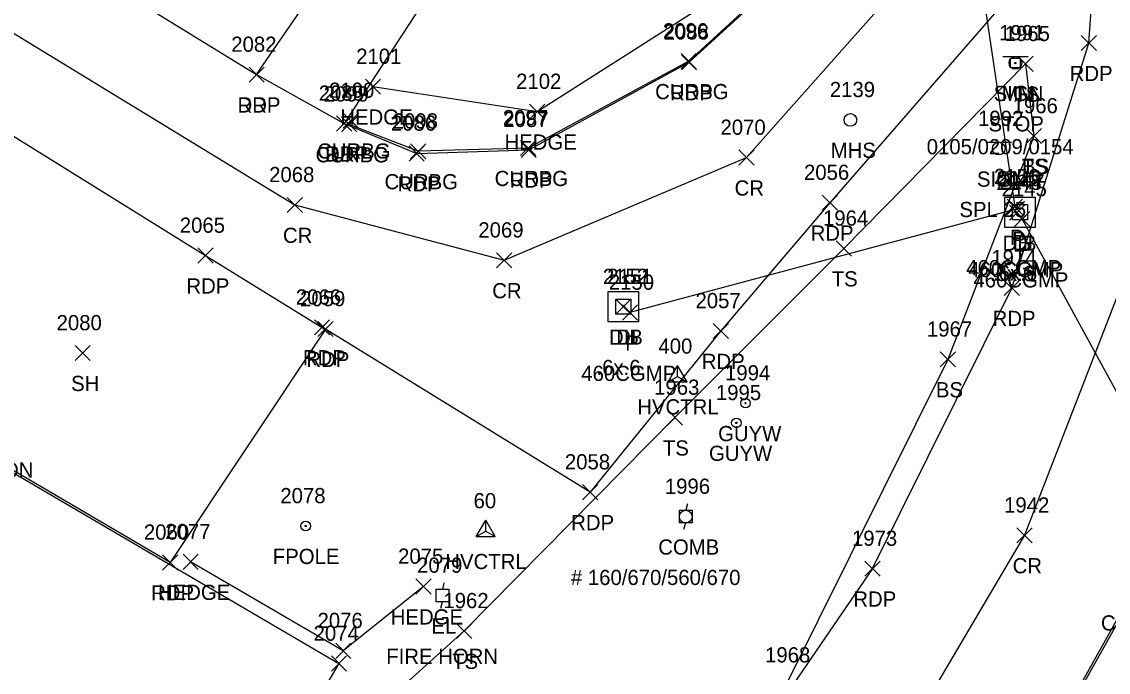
# Model space of a CAD drawing. Extents: x 462930 to 463548, y 29607 to 30453.
# Drawn here: x 463350.88 to 463394.45, y 30200.82 to 30226.91 of the extents above; entities that cross this region are included whole.
import ezdxf

# ---------------------------------------------------------------- set-up
doc = ezdxf.new("R2010")
doc.units = 0
for name, color, linetype in [('C_A', 7, 'Continuous'), ('C_I', 7, 'Continuous'), ('CPSM', 7, 'Continuous'), ('D_A', 7, 'Continuous'), ('D_C', 7, 'Continuous'), ('D_I', 7, 'Continuous'), ('D_TIC', 7, 'Continuous'), ('DCP', 7, 'Continuous'), ('DS', 7, 'Continuous'), ('L_A', 7, 'Continuous'), ('L_C', 7, 'Continuous'), ('L_I', 7, 'Continuous'), ('L_TIC', 7, 'Continuous'), ('LAHR', 7, 'Continuous'), ('LBC', 7, 'Continuous'), ('LELB', 7, 'Continuous'), ('LFP', 7, 'Continuous'), ('P_A', 7, 'Continuous'), ('P_I', 7, 'Continuous'), ('P_TIC', 7, 'Continuous'), ('PET', 7, 'Continuous'), ('PRC', 7, 'Continuous'), ('R_A', 7, 'Continuous'), ('R_I', 7, 'Continuous'), ('R_TIC', 7, 'Continuous'), ('RC', 7, 'Continuous'), ('RDP', 7, 'Continuous'), ('S_A', 7, 'Continuous'), ('S_C', 7, 'Continuous'), ('S_I', 7, 'Continuous'), ('SRM', 7, 'Continuous'), ('SSGN', 7, 'Continuous'), ('U_A', 7, 'Continuous'), ('U_C', 7, 'Continuous'), ('U_I', 7, 'Continuous'), ('UEPT', 7, 'Continuous'), ('UP', 7, 'Continuous'), ('UPGW', 7, 'Continuous'), ('USMH', 7, 'Continuous')]:
    doc.layers.add(name, color=color, linetype=linetype)

msp = doc.modelspace()

# ---------------------------------------------------------------- linework, layer by layer
at = {"layer": 'CPSM'}
for p, q in [((463376.802, 30212.464), (463377.183, 30213.124)), ((463377.564, 30212.464), (463377.183, 30213.124)), ((463377.183, 30212.684), (463377.183, 30213.124)), ((463376.802, 30212.464), (463377.183, 30212.684)), ((463377.183, 30212.684), (463377.183, 30212.684)), ((463377.183, 30212.684), (463377.564, 30212.464)), ((463376.802, 30212.464), (463377.564, 30212.464)), ((463369.106, 30206.262), (463369.487, 30206.922)), ((463369.868, 30206.262), (463369.487, 30206.922)), ((463369.487, 30206.482), (463369.487, 30206.922)), ((463369.106, 30206.262), (463369.487, 30206.482)), ((463369.487, 30206.482), (463369.487, 30206.482)), ((463369.487, 30206.482), (463369.868, 30206.262)), ((463369.106, 30206.262), (463369.868, 30206.262))]:
    msp.add_line(p, q, dxfattribs=at)
at = {"layer": 'D_TIC'}
for points in [[(463390.401, 30219.179), (463391.011, 30219.789)], [(463391.011, 30219.179), (463390.401, 30219.789)], [(463390.485, 30218.946), (463391.095, 30219.556)], [(463391.095, 30218.946), (463390.485, 30219.556)], [(463390.488, 30219.101), (463391.098, 30219.711)], [(463391.098, 30219.101), (463390.488, 30219.711)], [(463390.691, 30218.692), (463391.301, 30219.302)], [(463391.301, 30218.692), (463390.691, 30219.302)], [(463374.703, 30215.176), (463375.313, 30215.786)], [(463375.313, 30215.176), (463374.703, 30215.786)], [(463374.966, 30214.942), (463375.576, 30215.552)], [(463375.576, 30214.942), (463374.966, 30215.552)]]:
    msp.add_lwpolyline(points, dxfattribs=at)
at = {"layer": 'DCP'}
for points in [[(463388.16, 30236.54), (463390.706, 30219.484)], [(463390.793, 30219.406), (463375.271, 30215.247)], [(463390.996, 30218.997), (463401.362, 30200.025)]]:
    msp.add_lwpolyline(points, dxfattribs=at)
at = {"layer": 'DS'}
for p, q in [((463390.301, 30219.881), (463391.52, 30219.881)), ((463390.301, 30218.662), (463390.301, 30219.881)), ((463390.606, 30218.967), (463390.606, 30219.576)), ((463390.606, 30219.576), (463391.215, 30219.576)), ((463391.215, 30219.576), (463391.215, 30218.967)), ((463391.52, 30219.881), (463391.52, 30218.662)), ((463390.912, 30219.272), (463390.912, 30219.272)), ((463390.912, 30219.272), (463390.912, 30219.272)), ((463391.52, 30218.662), (463390.301, 30218.662)), ((463391.215, 30218.967), (463390.606, 30218.967)), ((463374.397, 30216.09), (463375.616, 30216.09)), ((463374.397, 30214.871), (463374.397, 30216.09)), ((463375.616, 30216.09), (463375.616, 30214.871)), ((463374.702, 30215.176), (463374.702, 30215.785)), ((463374.702, 30215.785), (463375.311, 30215.785)), ((463375.311, 30215.785), (463375.311, 30215.176)), ((463375.311, 30215.176), (463374.702, 30215.176)), ((463375.008, 30215.481), (463375.008, 30215.481)), ((463375.008, 30215.481), (463375.008, 30215.481)), ((463375.616, 30214.871), (463374.397, 30214.871))]:
    msp.add_line(p, q, dxfattribs=at)
at = {"layer": 'L_TIC'}
for points in [[(463390.828, 30224.915), (463391.438, 30225.525)], [(463391.438, 30224.915), (463390.828, 30225.525)], [(463364.661, 30224.003), (463365.271, 30224.613)], [(463365.271, 30224.003), (463364.661, 30224.613)], [(463371.247, 30223), (463371.857, 30223.61)], [(463371.857, 30223), (463371.247, 30223.61)], [(463391.164, 30222.022), (463391.774, 30222.632)], [(463391.774, 30222.022), (463391.164, 30222.632)], [(463391.164, 30222.022), (463391.774, 30222.632)], [(463391.774, 30222.022), (463391.164, 30222.632)], [(463383.543, 30217.513), (463384.153, 30218.123)], [(463384.153, 30217.513), (463383.543, 30218.123)], [(463353.018, 30213.318), (463353.628, 30213.928)], [(463353.628, 30213.318), (463353.018, 30213.928)], [(463387.71, 30213.065), (463388.32, 30213.675)], [(463388.32, 30213.065), (463387.71, 30213.675)], [(463376.772, 30210.73), (463377.382, 30211.34)], [(463377.382, 30210.73), (463376.772, 30211.34)], [(463357.35, 30204.94), (463357.96, 30205.55)], [(463357.96, 30204.94), (463357.35, 30205.55)], [(463366.686, 30203.954), (463367.296, 30204.564)], [(463367.296, 30203.954), (463366.686, 30204.564)], [(463368.32, 30202.172), (463368.93, 30202.782)], [(463368.93, 30202.172), (463368.32, 30202.782)], [(463363.472, 30201.375), (463364.082, 30201.985)], [(463364.082, 30201.375), (463363.472, 30201.985)], [(463363.299, 30200.864), (463363.909, 30201.474)], [(463363.909, 30200.864), (463363.299, 30201.474)]]:
    msp.add_lwpolyline(points, dxfattribs=at)
at = {"layer": 'LAHR'}
for points in [[(463364.966, 30224.308), (463371.552, 30223.305), (463380.488, 30229.022), (463384.199, 30233.617), (463377.592, 30237.674), (463372.069, 30241.574)], [(463366.991, 30204.259), (463363.777, 30201.68), (463357.655, 30205.245)]]:
    msp.add_lwpolyline(points, dxfattribs=at)
at = {"layer": 'LBC'}
for points in [[(463346.182, 30211.369), (463363.604, 30201.169)], [(463363.604, 30201.169), (463356.632, 30189.385)]]:
    msp.add_lwpolyline(points, dxfattribs=at)
at = {"layer": 'LELB'}
for points in [[(463363.492, 30197.847), (463368.625, 30202.477), (463377.077, 30211.035), (463383.848, 30217.818), (463391.133, 30225.22), (463391.469, 30222.327)], [(463391.469, 30222.327), (463388.015, 30213.37), (463381.524, 30200.3), (463373.809, 30189.987), (463366.273, 30181.173), (463359.853, 30172.726), (463354.448, 30169.466)]]:
    msp.add_lwpolyline(points, dxfattribs=at)
at = {"layer": 'LFP'}
for radius in [0.191, 0.0254]:
    msp.add_circle((463362.269, 30206.686), radius, dxfattribs=at)
at = {"layer": 'P_TIC'}
for points in [[(463393.366, 30225.751), (463393.976, 30226.361)], [(463393.976, 30225.751), (463393.366, 30226.361)], [(463377.336, 30224.978), (463377.946, 30225.588)], [(463377.946, 30224.978), (463377.336, 30225.588)], [(463359.997, 30224.485), (463360.607, 30225.095)], [(463360.607, 30224.485), (463359.997, 30225.095)], [(463363.505, 30222.524), (463364.115, 30223.134)], [(463364.115, 30222.524), (463363.505, 30223.134)], [(463370.907, 30221.47), (463371.517, 30222.08)], [(463371.517, 30221.47), (463370.907, 30222.08)], [(463366.414, 30221.322), (463367.024, 30221.932)], [(463367.024, 30221.322), (463366.414, 30221.932)], [(463379.641, 30221.157), (463380.251, 30221.767)], [(463380.251, 30221.157), (463379.641, 30221.767)], [(463382.979, 30219.349), (463383.589, 30219.959)], [(463383.589, 30219.349), (463382.979, 30219.959)], [(463361.53, 30219.258), (463362.14, 30219.868)], [(463362.14, 30219.258), (463361.53, 30219.868)], [(463357.947, 30217.228), (463358.557, 30217.838)], [(463358.557, 30217.228), (463357.947, 30217.838)], [(463369.921, 30217.038), (463370.531, 30217.648)], [(463370.531, 30217.038), (463369.921, 30217.648)], [(463390.276, 30215.926), (463390.886, 30216.536)], [(463390.886, 30215.926), (463390.276, 30216.536)], [(463362.618, 30214.348), (463363.228, 30214.958)], [(463363.228, 30214.348), (463362.618, 30214.958)], [(463362.759, 30214.281), (463363.369, 30214.891)], [(463363.369, 30214.281), (463362.759, 30214.891)], [(463378.613, 30214.203), (463379.223, 30214.813)], [(463379.223, 30214.203), (463378.613, 30214.813)], [(463373.375, 30207.738), (463373.985, 30208.348)], [(463373.985, 30207.738), (463373.375, 30208.348)], [(463390.79, 30206.007), (463391.4, 30206.617)], [(463391.4, 30206.007), (463390.79, 30206.617)], [(463356.532, 30204.919), (463357.142, 30205.529)], [(463357.142, 30204.919), (463356.532, 30205.529)], [(463384.69, 30204.671), (463385.3, 30205.281)], [(463385.3, 30204.671), (463384.69, 30205.281)]]:
    msp.add_lwpolyline(points, dxfattribs=at)
at = {"layer": 'PET'}
for points in [[(463351.849, 30230.001), (463360.302, 30224.79), (463363.81, 30222.829), (463366.719, 30221.627), (463371.212, 30221.775), (463377.641, 30225.283), (463383.918, 30231.013), (463388.099, 30237.45), (463392.941, 30245.442), (463393.346, 30254.193)], [(463357.128, 30146.779), (463364.23, 30160.089), (463372.211, 30170.687), (463380.439, 30181.089), (463388.986, 30192.495), (463395.438, 30204.072), (463399.65, 30216.413), (463402.389, 30229.411), (463403.525, 30242.02), (463404.007, 30246.74), (463403.926, 30248.538), (463404.123, 30251.434)], [(463384.995, 30204.976), (463390.581, 30216.231), (463393.671, 30226.056), (463394.127, 30232.442)], [(463391.243, 30228.803), (463383.284, 30219.654), (463378.918, 30214.508), (463373.68, 30208.043), (463363.064, 30214.586), (463356.837, 30205.224), (463346.241, 30211.421)], [(463347.352, 30224.297), (463358.252, 30217.533), (463362.923, 30214.653)], [(463384.995, 30204.976), (463376.26, 30192.198)]]:
    msp.add_lwpolyline(points, dxfattribs=at)
at = {"layer": 'PRC'}
for points in [[(463399.789, 30246.987), (463397.991, 30230.027), (463395.304, 30217.172), (463391.095, 30206.312), (463384.492, 30195.113), (463376.573, 30184.227), (463367.848, 30173.371), (463360.659, 30162.372), (463353.283, 30149.309)], [(463348.312, 30227.836), (463361.835, 30219.563), (463370.226, 30217.343), (463379.946, 30221.462), (463388.333, 30230.936), (463392.855, 30237.8)]]:
    msp.add_lwpolyline(points, dxfattribs=at)
at = {"layer": 'R_TIC'}
for points in [[(463377.322, 30225.023), (463377.932, 30225.633)], [(463377.932, 30225.023), (463377.322, 30225.633)], [(463359.997, 30224.485), (463360.607, 30225.095)], [(463360.607, 30224.485), (463359.997, 30225.095)], [(463363.505, 30222.524), (463364.115, 30223.134)], [(463364.115, 30222.524), (463363.505, 30223.134)], [(463363.704, 30222.49), (463364.314, 30223.1)], [(463364.314, 30222.49), (463363.704, 30223.1)], [(463363.771, 30222.64), (463364.381, 30223.25)], [(463364.381, 30222.64), (463363.771, 30223.25)], [(463370.886, 30221.54), (463371.496, 30222.15)], [(463371.496, 30221.54), (463370.886, 30222.15)], [(463366.472, 30221.409), (463367.082, 30222.019)], [(463367.082, 30221.409), (463366.472, 30222.019)]]:
    msp.add_lwpolyline(points, dxfattribs=at)
at = {"layer": 'RC'}
for points in [[(463403.888, 30243.164), (463403.731, 30243.164), (463403.598, 30241.759), (463402.492, 30229.375), (463399.74, 30216.359), (463395.506, 30204.018), (463389.016, 30192.435), (463380.487, 30181.016), (463372.297, 30170.609), (463364.316, 30160.034), (463357.246, 30146.767)], [(463387.898, 30237.519), (463387.999, 30237.434), (463383.852, 30231.054), (463377.627, 30225.328), (463371.191, 30221.845), (463366.777, 30221.714), (463364.009, 30222.795), (463364.076, 30222.945)]]:
    msp.add_lwpolyline(points, dxfattribs=at)
at = {"layer": 'RDP'}
msp.add_lwpolyline([(463360.302, 30224.79), (463368.01, 30236.004), (463371.141, 30234.059), (463363.81, 30222.829)], dxfattribs=at)
at = {"layer": 'SRM'}
msp.add_lwpolyline([(463390.533, 30225.445), (463390.915, 30225.445), (463390.915, 30225.063), (463390.533, 30225.063)], close=True, dxfattribs=at)
msp.add_circle((463390.724, 30225.254), 0.0254, dxfattribs=at)
at = {"layer": 'SSGN'}
for p, q in [((463390.228, 30225.514), (463391.244, 30225.514)), ((463390.73, 30225.26), (463390.73, 30225.26)), ((463389.556, 30222.079), (463390.572, 30222.079)), ((463390.058, 30221.825), (463390.058, 30221.825))]:
    msp.add_line(p, q, dxfattribs=at)
for centre in [(463390.73, 30225.26), (463390.058, 30221.825)]:
    msp.add_circle(centre, 0.254, dxfattribs=at)
at = {"layer": 'UEPT'}
for p, q in [((463367.808, 30204.404), (463367.757, 30204.15)), ((463367.503, 30203.642), (463367.503, 30204.15)), ((463367.503, 30204.15), (463368.011, 30204.15)), ((463367.757, 30203.896), (463367.757, 30203.896)), ((463368.011, 30204.15), (463368.011, 30203.642)), ((463368.011, 30203.642), (463367.503, 30203.642)), ((463367.681, 30203.388), (463367.757, 30203.642))]:
    msp.add_line(p, q, dxfattribs=at)
at = {"layer": 'UP'}
for p, q in [((463377.255, 30206.808), (463377.255, 30207.316)), ((463377.255, 30207.316), (463377.763, 30207.316)), ((463377.585, 30207.57), (463377.509, 30207.316)), ((463377.763, 30207.316), (463377.763, 30206.808)), ((463377.509, 30207.062), (463377.509, 30207.062)), ((463377.763, 30206.808), (463377.255, 30206.808)), ((463377.433, 30206.554), (463377.509, 30206.808))]:
    msp.add_line(p, q, dxfattribs=at)
msp.add_circle((463377.509, 30207.062), 0.254, dxfattribs=at)
at = {"layer": 'UPGW'}
for centre, radius in [((463379.906, 30211.612), 0.191), ((463379.906, 30211.612), 0.0254), ((463379.539, 30210.821), 0.191), ((463379.539, 30210.821), 0.0254)]:
    msp.add_circle(centre, radius, dxfattribs=at)
at = {"layer": 'USMH'}
for p, q in [((463384.109, 30222.974), (463384.109, 30222.974)), ((463384.363, 30222.974), (463384.363, 30222.974))]:
    msp.add_line(p, q, dxfattribs=at)
msp.add_circle((463384.109, 30222.974), 0.254, dxfattribs=at)

# ---------------------------------------------------------------- texts
at = {"layer": 'C_A'}
for p in [(463375.565, 30211.16), (463367.869, 30204.958)]:
    msp.add_text('HVCTRL', height=0.6096, dxfattribs=at).set_placement(p)
at = {"layer": 'C_I'}
for s, p in [('400', (463376.413, 30213.598)), ('60', (463369, 30207.396))]:
    msp.add_text(s, height=0.6096, dxfattribs=at).set_placement(p)
at = {"layer": 'D_A'}
for s, height, p in [('DIB', 0.6096, (463390.212, 30217.727)), ('P', 0.61, (463390.516, 30217.96)), ('P', 0.61, (463390.603, 30217.882)), ('DI', 0.6096, (463390.624, 30217.748)), ('P', 0.61, (463390.806, 30217.473)), ('DIB', 0.6096, (463374.43, 30213.957)), ('DI', 0.6096, (463374.72, 30213.957)), ('P', 0.61, (463375.081, 30213.723))]:
    msp.add_text(s, height=height, dxfattribs=at).set_placement(p)
at = {"layer": 'D_C'}
for s, p in [('460CGMP', (463388.755, 30216.741)), ('460CGMP', (463388.842, 30216.663)), ('460CGMP', (463389.045, 30216.254)), ('.6x.6', (463389.712, 30216.508)), ('.6x.6', (463389.834, 30216.529)), ('.6x.6', (463373.93, 30212.738)), ('460CGMP', (463373.32, 30212.504))]:
    msp.add_text(s, height=0.6096, dxfattribs=at).set_placement(p)
at = {"layer": 'D_I'}
for s, p in [('2156', (463389.868, 30220.398)), ('2148', (463389.969, 30220.165)), ('2149', (463389.97, 30220.32)), ('2147', (463390.091, 30220.186)), ('2145', (463390.175, 30219.911)), ('2152', (463374.187, 30216.395)), ('2151', (463374.36, 30216.395)), ('2150', (463374.424, 30216.161))]:
    msp.add_text(s, height=0.6096, dxfattribs=at).set_placement(p)
at = {"layer": 'L_A'}
for s, p in [('TS', (463390.648, 30223.696)), ('HEDGE', (463363.656, 30222.784)), ('HEDGE', (463370.242, 30221.781)), ('TS', (463390.984, 30220.803)), ('BS', (463390.994, 30220.803)), ('TS', (463383.363, 30216.294)), ('SH', (463352.862, 30212.099)), ('BS', (463387.54, 30211.846)), ('TS', (463376.592, 30209.511)), ('FPOLE', (463360.949, 30205.162)), ('HEDGE', (463356.345, 30203.721)), ('HEDGE', (463365.681, 30202.735)), ('TS', (463368.14, 30200.953))]:
    msp.add_text(s, height=0.6096, dxfattribs=at).set_placement(p)
at = {"layer": 'L_C'}
msp.add_text('READSBORO FIRE STATION', height=0.6096, dxfattribs=at).set_placement((463340.3, 30208.626))
at = {"layer": 'L_I'}
for s, p in [('1965', (463390.298, 30226.134)), ('2101', (463364.294, 30225.222)), ('2102', (463370.707, 30224.219)), ('1966', (463390.617, 30223.241)), ('1966', (463390.617, 30223.241)), ('1964', (463383.013, 30218.732)), ('2080', (463352.279, 30214.537)), ('1967', (463387.18, 30214.284)), ('1963', (463376.242, 30211.949)), ('2078', (463361.251, 30207.6)), ('2077', (463356.637, 30206.159)), ('2075', (463365.973, 30205.173)), ('1962', (463367.79, 30203.391)), ('2076', (463362.743, 30202.594)), ('2074', (463362.586, 30202.083)), ('1968', (463380.689, 30201.214))]:
    msp.add_text(s, height=0.6096, dxfattribs=at).set_placement(p)
at = {"layer": 'P_A'}
for s, p in [('RDP', (463392.905, 30224.532)), ('RDP', (463376.875, 30223.759)), ('RDP', (463359.536, 30223.266)), ('RDP', (463363.044, 30221.305)), ('RDP', (463370.446, 30220.251)), ('RDP', (463365.953, 30220.103)), ('CR', (463379.468, 30219.938)), ('CR', (463361.357, 30218.039)), ('RDP', (463382.518, 30218.13)), ('RDP', (463357.486, 30216.009)), ('CR', (463369.748, 30215.819)), ('RDP', (463389.815, 30214.707)), ('RDP', (463362.157, 30213.129)), ('RDP', (463362.298, 30213.062)), ('RDP', (463378.152, 30212.984)), ('RDP', (463372.914, 30206.519)), ('CR', (463390.617, 30204.788)), ('RDP', (463356.071, 30203.7)), ('RDP', (463384.229, 30203.452))]:
    msp.add_text(s, height=0.6096, dxfattribs=at).set_placement(p)
at = {"layer": 'P_I'}
for s, p in [('2088', (463376.623, 30226.197)), ('2082', (463359.284, 30225.704)), ('2085', (463362.792, 30223.743)), ('2086', (463365.685, 30222.541)), ('2087', (463370.194, 30222.689)), ('2070', (463378.902, 30222.376)), ('2068', (463360.803, 30220.477)), ('2056', (463382.25, 30220.568)), ('2065', (463357.22, 30218.447)), ('2069', (463369.192, 30218.257)), ('1974', (463389.76, 30217.145)), ('2066', (463361.874, 30215.567)), ('2059', (463362.044, 30215.5)), ('2057', (463377.9, 30215.422)), ('2058', (463372.662, 30208.957)), ('1942', (463390.274, 30207.226)), ('2060', (463355.779, 30206.138)), ('1973', (463384.174, 30205.89))]:
    msp.add_text(s, height=0.6096, dxfattribs=at).set_placement(p)
at = {"layer": 'R_A'}
for s, p in [('CURBG', (463376.281, 30223.804)), ('DRP', (463359.536, 30223.266)), ('CURBG', (463362.663, 30221.271)), ('CURBG', (463362.73, 30221.421)), ('DRP', (463363.044, 30221.305)), ('CURBG', (463365.431, 30220.19)), ('CURBG', (463369.845, 30220.321)), ('CURBG', (463394.16, 30202.494))]:
    msp.add_text(s, height=0.6096, dxfattribs=at).set_placement(p)
at = {"layer": 'R_I'}
for s, p in [('2096', (463376.593, 30226.242)), ('2082', (463359.284, 30225.704)), ('2085', (463362.792, 30223.743)), ('2099', (463362.989, 30223.709)), ('2100', (463363.205, 30223.859)), ('2097', (463370.173, 30222.759)), ('2098', (463365.759, 30222.628))]:
    msp.add_text(s, height=0.6096, dxfattribs=at).set_placement(p)
at = {"layer": 'S_A'}
for s, p in [('SIGN', (463389.858, 30223.73)), ('MM', (463390.172, 30223.73)), ('SIGN', (463389.186, 30220.295))]:
    msp.add_text(s, height=0.6096, dxfattribs=at).set_placement(p)
at = {"layer": 'S_C'}
for s, p in [('STOP', (463389.651, 30222.511)), ('0105/0209/0154', (463387.172, 30221.596)), ('SPL 25', (463388.482, 30219.076))]:
    msp.add_text(s, height=0.6096, dxfattribs=at).set_placement(p)
at = {"layer": 'S_I'}
for s, p in [('1991', (463390.076, 30226.168)), ('1991', (463390.076, 30226.168)), ('1992', (463389.231, 30222.733))]:
    msp.add_text(s, height=0.6096, dxfattribs=at).set_placement(p)
at = {"layer": 'U_A'}
for s, p in [('MHS', (463383.322, 30221.45)), ('GUYW', (463378.807, 30210.088)), ('GUYW', (463378.44, 30209.297)), ('COMB', (463376.407, 30205.538)), ('EL', (463367.311, 30202.372))]:
    msp.add_text(s, height=0.6096, dxfattribs=at).set_placement(p)
at = {"layer": 'U_C'}
for s, p in [('# 160/670/560/670', (463372.904, 30204.319)), ('FIRE HORN', (463365.499, 30201.153))]:
    msp.add_text(s, height=0.6096, dxfattribs=at).set_placement(p)
at = {"layer": 'U_I'}
for s, p in [('2139', (463383.286, 30223.888)), ('1994', (463379.085, 30212.526)), ('1995', (463378.718, 30211.735)), ('1996', (463376.671, 30207.976)), ('2079', (463366.737, 30204.81))]:
    msp.add_text(s, height=0.6096, dxfattribs=at).set_placement(p)

doc.saveas('drawing.dxf')
